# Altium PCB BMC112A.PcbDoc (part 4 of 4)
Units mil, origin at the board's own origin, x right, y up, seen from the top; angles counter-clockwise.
Board outline 5600 x 6100 mil, 8 copper layers (Top Layer, Signal Layer 1, Signal Layer 2, Signal Layer 3, Signal Layer 4, Signal Layer 5, Signal Layer 6, Bottom Layer), stack 62.048 mil thick; 366 components, 158 nets, 872 pads, 1045 vias.
Unrouted connection lines stored in the file: 4.
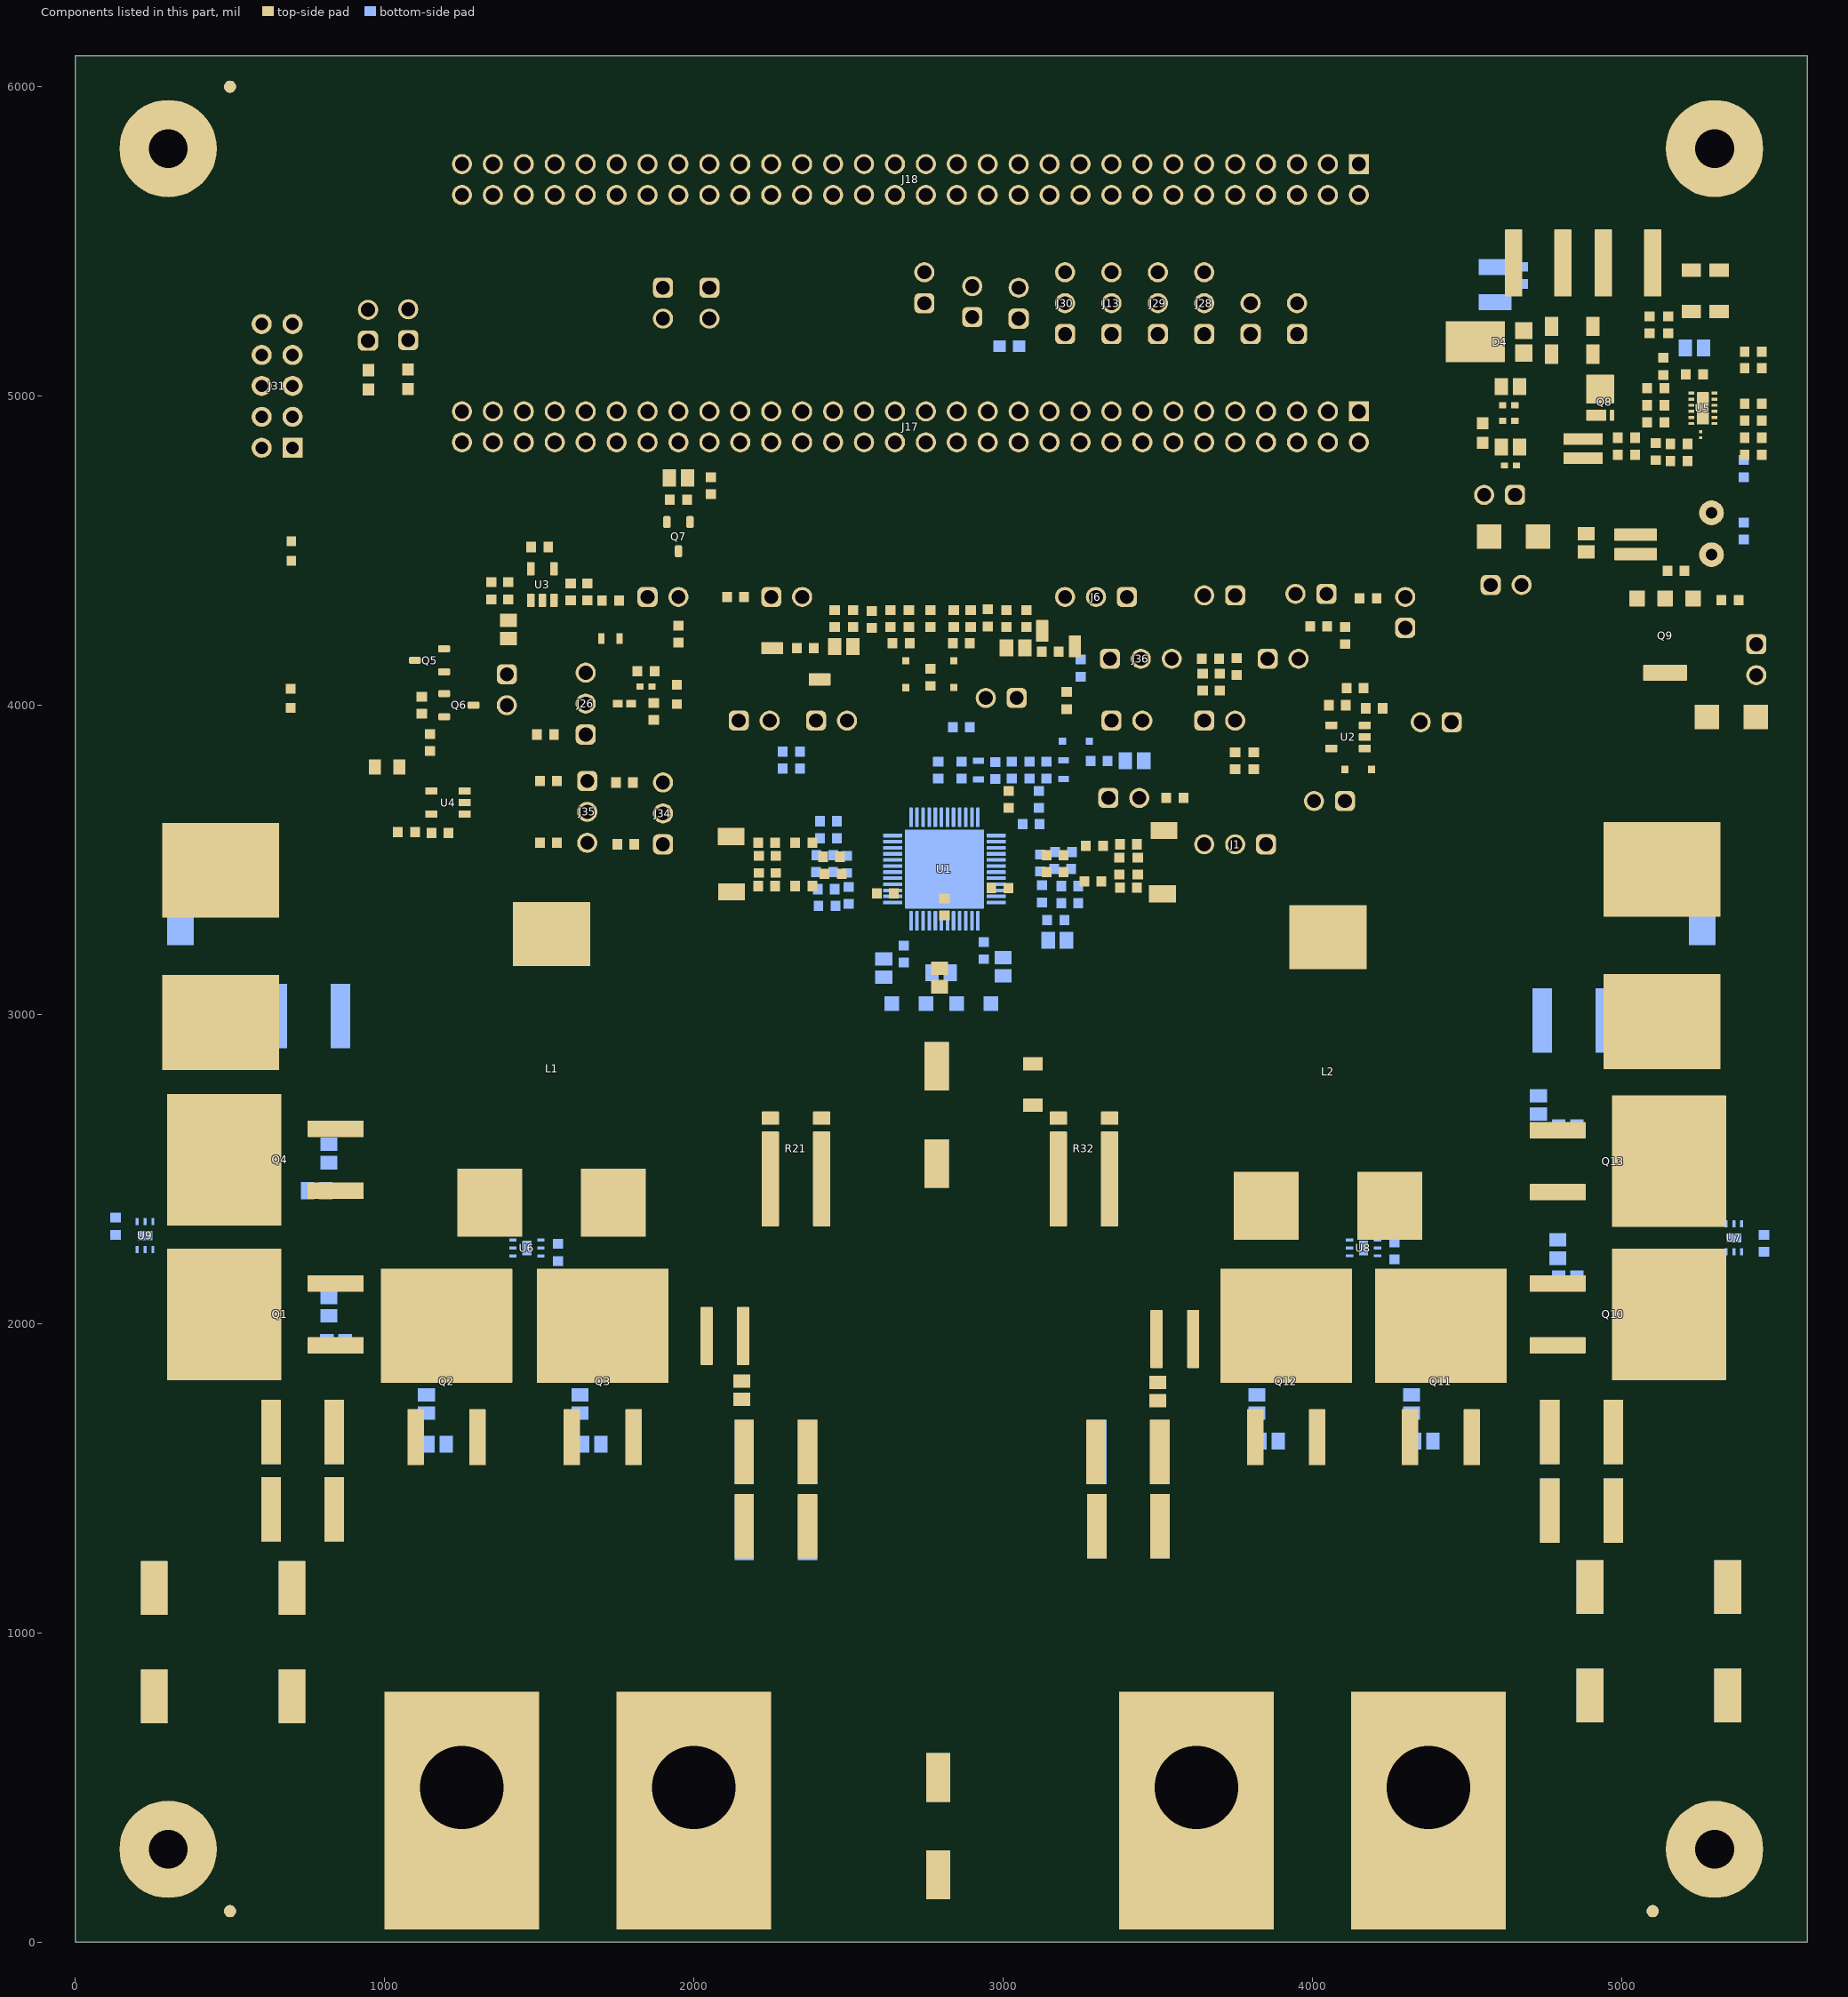
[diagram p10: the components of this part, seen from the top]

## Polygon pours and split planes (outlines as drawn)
NetC85_2 on Top Layer "TOP_LAYER_NETC85_2_P838" (solid, remove dead copper, pour order 838): 2092.06,3601.19 2137.72,3601.19 2137.72,3557.84 2092.06,3557.84
V48 on Top Layer "TOP_LAYER_V48_P849" (solid, remove dead copper, pour order 849): 1644.68,31.5 1644.41,31.77 1644.41,862.2 865.16,862.2 865.16,30
PGND on Top Layer "Signal Layer 1-PGND" (solid, remove dead copper, pour order 856): 5600,10 5600,6070 4390,6070 4390,5195 4390,3700 4030,3340 2820,3340 2310,3340 2140,3510 1055,3510 655,3910 655,6085 0,6085 0,10
AGND on Top Layer "Top Layer-AGND" (solid, remove dead copper, pour order 855): 1167.35,6076.65 667.38,6076.65 667.38,3921.65 1067.38,3521.65 1937.38,3521.65 2109.87,3349.15 4024.88,3349.15 4522.38,3846.65 4522.38,4339.46 4372.38,4489.46 4372.38,6076.65
V12 on Top Layer "Top Layer-V12" (solid, remove dead copper, pour order 854): 4015,25.26 3374.74,25.26 3040,360 2500,360 2315,545 2315,2730 3285,2730 3285,2280 3360,2205 3360,1540 3360,1220 3407.07,1172.93 3762.07,1172.93 4015,920
V48 on Top Layer "Top Layer-V48-2" (solid, remove dead copper, pour order 853): 5555,940 4891.63,940 4891.63,3130 5555,3130
V48 on Top Layer "Top Layer-V48-1" (solid, remove dead copper, pour order 852): 740,940 55,940 55,3130 740,3130
SW1 on Top Layer "Top Layer-No Net 10" (solid, remove dead copper, pour order 851): 2080,1840 2080,2200 2043.26,2236.74 1616.74,2236.74 1570,2283.49 1570,2750 1553.26,2766.74 786.74,2766.74 750,2730 750,1845 788.26,1806.74 2046.74,1806.74
SW2 on Top Layer "Top Layer-SW2" (solid, remove dead copper, pour order 850): 4020,2730 4020,2280 3973.67,2233.67 3608.67,2233.67 3570,2195 3570,1860 3620.47,1809.53 4804.53,1809.53 4881.33,1886.33 4881.33,2708.67 4816.33,2773.67 4063.67,2773.67
NetL2_1 on Top Layer "Top Layer-NetL2-1" (solid, remove dead copper, pour order 848): 3330,2260 3960,2260 3990,2290 3990,2740 3960,2770 3330,2770 3300,2740 3300,2290
NetL1_2 on Top Layer "Top Layer-NetL1-2" (solid, remove dead copper, pour order 847): 1620,2270 2270,2270 2295,2295 2295,2735 2270,2760 1620,2760 1600,2740 1600,2290
NetC48_2 on Top Layer "TOP_LAYER_NETC48_2_P846" (solid, remove dead copper, pour order 846): 4632.5,5260 4632.5,4895 4387.5,4895 4387.5,5260
NetC46_1 on Top Layer "TOP_LAYER_NETC46_1_P845" (solid, remove dead copper, pour order 845): 4990,4975 4860,4975 4835,5000 4835,5235 4900,5300 4900,5560 4920,5580 5000,5580 5015,5565 5015,5000
NetC42_1 on Top Layer "TOP_LAYER_NETC42_1_P844" (solid, remove dead copper, pour order 844): 5175,5240 5073.4,5240 5073.4,5553.4 5085,5565 5340,5565 5353.39,5551.61 5353.39,5383.39 5345,5375 5225,5375 5185,5335 5185,5250
NetC41_2 on Top Layer "TOP_LAYER_NETC41_2_P843" (solid, remove dead copper, pour order 843): 4710,5565 4710,5350 4810,5250 4810,5105 4800,5095 4665,5095 4655,5105 4655,5260 4605,5310 4605,5565 4615,5575 4700,5575
NetD7_1 on Top Layer "TOP_LAYER_NETD7_1_P841" (solid, remove dead copper, pour order 841): 5318.73,3892.98 4973.11,3892.98 4973.11,4250 5318.73,4250
AGND2 on Top Layer "TOP_LAYER_AGND2_P208" (solid, remove dead copper, pour order 842): 5435,5155 5435,4865 5195,4865 5195,4730 5500,4730 5500,5155
NetQ8_1-2-3 on Top Layer "TOP_LAYER_NETQ8_1-2-3_P840" (solid, remove dead copper, pour order 840): 4947.59,4955 4947.59,4895 4937.59,4885 4937.59,4841.65 4792.59,4841.65 4792.59,4955
AGND on Signal Layer 1 "SIGNAL_LAYER_1_AGND_P857" (solid, remove dead copper, pour order 857): 529.04,5293.81 779.35,5293.81 779.35,4682.49 529.45,4682.49
PGND on Signal Layer 1 "Signal Layer 1-Pgnd" (solid, remove dead copper, pour order 859): 5600,10 5600,6075 4540,6075 4395,6075 4390,5215 4393.1,3703.1 4030,3340 2820,3340 2310,3340 2140,3510 1055,3510 655,3910 655,6075 1155,6075 0,6075 0,10
AGND on Signal Layer 1 "Top Layer-Agnd" (solid, remove dead copper, pour order 858): 1169.97,6075 670,6075 670,3924.74 1070.17,3525.08 1938.79,3526.21 2112.76,3352.24 4027.24,3352.24 4525,3850 4525,4333.68 4375,4483.68 4375,5555 4375,6075
PGND on Signal Layer 2 "Signal Layer 1-pgnd" (solid, remove dead copper, pour order 866): 5600,20 5600,6080 4540,6080 4390,6080 4390,5198.17 4390,3700 4040,3350 2805,3350 2295,3350 2135,3510 1055,3510 655,3910 655,6080 1140,6080 0,6080 0,20
SW2 on Signal Layer 2 "SIGNAL_LAYER_2_SW2_P863" (solid, remove dead copper, pour order 863): 4850,2150 4650,2150 4650,1810 3500,1810 3500,2200 4020,2200 4020,2775 4850,2775
SW1 on Signal Layer 2 "SIGNAL_LAYER_2_SW1_P862" (solid, remove dead copper, pour order 862): 1885,1805 780,1805 750,1835 750,2735 780,2765 1495,2765 1570,2690 1570,2205 1875,2205 1920,2160 1920,1840
AGND on Signal Layer 2 "Top Layer-NetAGND 6" (solid, remove dead copper, pour order 865): 660,6070 660,3905 1060,3505 1930,3505 2102.76,3332.24 4017.24,3332.24 4515,3830 4515,4343.68 4375,4483.68 4375,6070
V12 on Signal Layer 2 "Top Layer-Net V1213" (solid, remove dead copper, pour order 864): 4015,25.26 3450,25.26 3115.26,360 2500,360 2315,545 2315,2730 3285,2730 3285,2280 3360,2205 3360,1215 3400,1175 3725,1175 4015,885
NetL2_1 on Signal Layer 2 "Signal Layer 2- NetL2-1 7" (solid, remove dead copper, pour order 861): 3410,2760 3980,2760 3995,2745 3995,2265 3975,2245 3415,2245 3395,2265 3395,2745
NetL1_2 on Signal Layer 2 "Signal Layer 2-NetL1-2 7" (solid, remove dead copper, pour order 860): 1630,2760 2175,2760 2200,2735 2200,2265 2180,2245 1620,2245 1600,2265 1600,2730
V48 on Signal Layer 3 "Signal Layer 3-V48" (solid, remove dead copper, pour order 871): 5600,25 1425,25 1420,30 0,30 0,2980 5600,2980
AGND on Signal Layer 3 "Top Layer-AGND 6" (solid, remove dead copper, pour order 870): 1121.31,6020.98 621.35,6020.98 621.35,3870.69 1021.37,3471.21 1894.94,3472.39 2069.11,3298.22 3978.58,3298.22 4476.35,3795.98 4476.35,4278.46 4326.35,4428.46 4326.35,6020.98
PGND on Signal Layer 3 "Signal Layer 3- PGND 1" (solid, remove dead copper, pour order 869): 4542.25,6075 5600,6075 5600,2995 0,2995 0,6075 1172.33,6075 655,6075 655,3910 1055,3510 1935,3510 2096.88,3348.12 4038.12,3348.12 4395,3705 4395,5195 4395,6075
SW1 on Signal Layer 3 "Top Layer-No Net 10" (solid, remove dead copper, pour order 868): 2080,1830 2080,2200 2050,2230 1630,2230 1600,2260 1600,2680 1565,2715 965,2715 932.64,2682.64 932.64,1827.36 960,1800 2050,1800
SW2 on Signal Layer 3 "Top Layer- NetSW-2 5" (solid, remove dead copper, pour order 867): 3995,2675 3995,2223.67 3613.67,2223.67 3570,2180 3570,1840 3606.33,1803.67 4633.67,1803.67 4670,1840 4670,2680 4635,2715 4035,2715
PGND on Signal Layer 4 "Signal Layer 1-PGND" (solid, remove dead copper, pour order 873): 5600.39,10 5600.39,6075 4389.93,6075 4389.93,3699.93 4030,3340 2820,3340 2105,3340 1930,3515 1050,3515 655,3910 655,6075 0,6075 0,10
AGND on Signal Layer 4 "Top Layer-AGND" (solid, remove dead copper, pour order 872): 1169.97,6075 670,6075 670,3924.65 1070.05,3525.15 1938.67,3526.33 2112.76,3352.24 4027.24,3352.24 4525,3850 4525,4333.68 4375,4483.68 4375,6075
V48 on Signal Layer 5 "Signal Layer 3-V48" (solid, remove dead copper, pour order 878): 5600.39,30 1430,30 1425,35 1.97,35 1.97,2980 5600.39,2980
AGND on Signal Layer 5 "Top Layer-AGND 6" (solid, remove dead copper, pour order 877): 1170,6075 670,6075 670,3930 1075,3525 1940,3525 2112.76,3352.24 4027.24,3352.24 4525.9,3850.9 4521.59,4325.1 4375,4487.4 4375,5570 4525,5730 4525,6075
PGND on Signal Layer 5 "Signal Layer 3-PGND 1" (solid, remove dead copper, pour order 876): 4392.17,6075 5600.39,6075 5600.39,2991 1.97,2991 1.97,6075 1155,6075 655,6075 655,3905 1050,3510 1935,3510 2102.3,3342.7 4032.7,3342.7 4388.6,3698.6
SW1 on Signal Layer 5 "Top Layer-SW1 10" (solid, remove dead copper, pour order 875): 2088.11,1838.11 2088.11,2199.88 2057.99,2230 1590,2230 1590,2660 1535,2715 980,2715 932.64,2667.64 932.64,1857.36 990,1800 2050,1800
SW2 on Signal Layer 5 "Top Layer-SW2 5" (solid, remove dead copper, pour order 874): 4010,2680 4010,2223.67 3598.48,2223.67 3566.89,2192.07 3566.89,1843.11 3606.33,1803.67 4623.67,1803.67 4670,1850 4670,2680 4630,2720 4050,2720
PGND on Signal Layer 6 "Signal Layer 6 PGND" (solid, remove dead copper, pour order 880): 5600.39,10 5600.39,6075 4389.93,6075 4389.93,3699.93 4030,3340 2820,3340 2105,3340 1935,3510 1055,3510 655,3910 655,6075 1155,6075 -3.94,6075 -3.94,10
AGND on Signal Layer 6 "Signal Layer 6 AGND" (solid, remove dead copper, pour order 879): 1170,6075 670,6075 670,3924.71 1070.08,3525.18 1938.62,3526.38 2112.76,3352.24 4027.24,3352.24 4525,3850 4525,4333.68 4375,4483.68 4375,6075
PGND on Bottom Layer "Bottom Layer PGND" (solid, remove dead copper, pour order 888): 5603.35,10 5603.35,6075 4390,6075 4390,3700 4030,3340 2820,3340 2105,3340 1935,3510 1055,3510 655,3910 655,6075 1.97,6075 1.97,10
AGND on Bottom Layer "Bottom Layer AGND" (solid, remove dead copper, pour order 887): 1169.97,6075 670,6075 670,3925 1070,3525 1940,3525 2113.45,3351.55 4026.55,3351.55 4525,3850 4525,4332.48 4375,4482.48 4375,6075
V12 on Bottom Layer "Top Layer-V12 3" (solid, remove dead copper, pour order 886): 4010,25.26 3374.74,25.26 3040,360 2510,360 2315,555 2315,2730 3285,2730 3285,2280 3360,2205 3360,1215 3405,1170 3765,1170 4010,925
V48 on Bottom Layer "Top Layer-V48 8" (solid, remove dead copper, pour order 885): 5555,940 4865,940 4865,3130 5555,3130
V48 on Bottom Layer "Top Layer-V48 7" (solid, remove dead copper, pour order 884): 740,940 55,940 55,3130 740,3130
SW1 on Bottom Layer "Top Layer-SW1" (solid, remove dead copper, pour order 883): 2080,1855.14 2080,2185.31 2030.31,2235 1615,2235 1570.56,2279.44 1570.56,2714.44 1520,2765 785,2765 750.56,2730.56 750.56,1879.44 825,1805 2029.86,1805
SW2 on Bottom Layer "Top Layer-SW2" (solid, remove dead copper, pour order 882): 4020,2730 4020,2276.56 3977.11,2233.67 3597.93,2233.67 3563.44,2199.18 3563.44,1846.56 3596.33,1813.67 4793.45,1813.67 4829.33,1849.55 4829.33,2737.28 4792.95,2773.67 4063.67,2773.67
AGND on Bottom Layer "Bottom Layer-AGND 1" (solid, remove dead copper, pour order 881): 2449.81,3335 2449.81,3634.81 2605,3790 3105,3790 3105,3195 3300,3195 3300,3910 2325,3910 2325,3335

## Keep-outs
Keep-Out Layer:
  the board outline again, w10
  text ".Layer_Name" at 373.26,-1656.72 h60

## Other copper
Top Layer:
  text ".Layer_Name" at 373.26,-1656.72 h60
Signal Layer 1:
  text ".Layer_Name" at 373.03,-1656.5 h60
Signal Layer 2:
  text ".Layer_Name" at 373.03,-1656.5 h60
Signal Layer 3:
  text ".Layer_Name" at 373.03,-1656.5 h60
Signal Layer 4:
  text ".Layer_Name" at 374.02,-1655.51 h60
Signal Layer 5:
  text ".Layer_Name" at 373.03,-1654.53 h60
Signal Layer 6:
  pour cut-out: 4720,5280 4740,5280 4750,5270 4750,5250 4740,5240 4720,5240 4710,5250 4710,5270
  text ".Layer_Name" at 374.02,-1654.53 h60
Bottom Layer:
  rectangle net AGND: 2792.61,3353.07 2852.61,3378.07
  pour cut-out: 4720,5280 4740,5280 4750,5270 4750,5250 4740,5240 4720,5240 4710,5250 4710,5270
  text ".Layer_Name" at 373.26,-1656.72 h60

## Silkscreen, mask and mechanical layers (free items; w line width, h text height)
Top Overlay:
  lines w7: 1119.25,5650 1181.69,5650 ; 1120.96,4849.54 1179.65,4849.54 ; 1955,5903.78 1955,5825 ; 4271.15,4846.45 4212.46,4846.45 ; 4280.43,5651.57 4221.74,5651.57 ; 5364.17,5212.13 5204.17,5202.13 ; 1179.65,4849.54 1160.14,4839.21 1160.35,4860.63 1179.65,4849.54 ; 1181.69,5650 1162.18,5638.91 1162.18,5661.09 1181.69,5650 ; 1955,5825 1964.78,5845 1945,5845 1955,5825 ; 4212.46,4846.45 4231.75,4835.36 4231.97,4856.78 4212.46,4846.45 ; 4221.74,5651.57 4241.03,5640.49 4241.25,5661.91 4221.74,5651.57 ; 5204.17,5202.13 5209.17,5207.13 5209.17,5197.13 5204.17,5202.13
  lines w10: 1162.65,1329.49 1161.94,1181.14 1790.6,1181.14 ; 1163.29,1331.38 1791.95,1331.38 ; 1791.26,1182.48 1791.98,1330.83 ; 3850.5,1329.25 3849.78,1180.91 4478.44,1180.91 ; 3851.13,1331.15 4479.79,1331.15 ; 4479.11,1182.25 4479.82,1330.59
  text "KEY" at 1280,5840 h40 r90
  text "DIR" at 3760,5840 h40 r90
  text "10V" at 2075,5835 h40 r90
  text "SDA" at 2275,5835 h40 r90
  text "ISETD" at 3580,5835 h40 r90
  text "ISETA" at 3670,5835 h40 r90
  text "SCL" at 2170,5830 h40 r90
  text "OPT" at 3270,5830 h40 r90
  text "V48_X" at 4175,5830 h40 r90
  text "SD_CMD_S" at 1819.7,5825 h40 r45
  text "IOUT1_X" at 2670,5825 h40 r90
  text "IOUT1_S" at 2875,5825 h40 r90
  text "5.0V" at 2970,5825 h40 r90
  text "CH1_S" at 3870,5825 h40 r90
  text "EN_S" at 3965,5825 h40 r90
  text "V12_X" at 4070,5825 h40 r90
  text "SECONDARY" at 4232.28,5825 h40
  text "PGND" at 2375,5820 h40 r90
  text "AGND" at 2470,5820 h40 r90
  text "IOUT2_X" at 2570,5820 h40 r90
  text "IOUT2_S" at 2770,5820 h40 r90
  text "DEM S" at 3075,5820 h40 r90
  text "CH2_S" at 3180,5820 h40 r90
  text "SYNIN_S" at 3470,5820 h40 r90
  text "SYNOT_S" at 3375,5815 h40 r90
  text "GND ROW" at 4300.29,5635.92 h35
  text "GND ROW" at 871.83,5634.58 h35
  text "4XPH" at 2670,5480 h40
  text "EN1" at 3520,5480 h40 r90
  text "EN2" at 3220,5470 h40 r90
  text "SYN" at 3370,5470 h40 r90
  text "DIR" at 3660,5470 h40 r90
  text "SSDEM" at 2851.81,5415 h40 r45
  text "SQIN" at 3060,5415 h40 r90
  text "SDA" at 899.73,5379.09 h35
  text "SCL" at 1040.59,5377.41 h35
  text "CH1_S" at 3820,5370 h40 r90
  text "EN_S" at 3960,5370 h40 r90
  text "10.0V" at 2160,5330 h40 r90
  text "nSD" at 1830,5300 h40 r90
  text "AGND" at 2470,5040 h40 r90
  text "PRIMARY" at 4181.45,5037.8 h40
  text "10V" at 2070,5030 h40 r90
  text "SDA" at 2270,5030 h40 r90
  text "PGND" at 2370,5030 h40 r90
  text "IOUT2_S" at 2570,5030 h40 r90
  text "IOUT1_S" at 2670,5030 h40 r90
  text "SD_CMD" at 1995,5025 h40 r90
  text "KEY" at 1270,5020 h40 r90
  text "SD_CMD_S" at 1370,5020 h40 r90
  text "SYNCOUT_S" at 1470,5020 h40 r90
  text "SYNCIN_S" at 1570,5020 h40 r90
  text "CH2_S" at 1670,5020 h40 r90
  text "CH1_S" at 1770,5020 h40 r90
  text "EN_S" at 1870,5020 h40 r90
  text "SCL" at 2170,5020 h40 r90
  text "GND ROW" at 864.23,4834.58 h35
  text "GND" at 4284.58,4828.8 h35
  text "EN1" at 3870,4680 h40 r90
  text "EN2" at 3170,4670 h40 r90
  text "DIR" at 3770,4670 h40 r90
  text "OPT" at 3265,4665 h40 r90
  text "5.0V" at 2980,4630 h40 r90
  text "DEM" at 3080,4630 h40 r90
  text "UVLO" at 3972.17,4624.13 h40 r90
  text "IOUT1" at 2870,4620 h40 r90
  text "SP_BIAS" at 4256.81,4603.5 h40
  text "IOUT2" at 2765,4595 h40 r90
  text "ISETD" at 3570,4590 h40 r90
  text "ISETA" at 3670,4590 h40 r90
  text "V12SNS" at 4079.96,4555.43 h40 r90
  text "SYNCIN" at 3470,4550 h40 r90
  text "V48SNS" at 4180.22,4550 h40 r90
  text "SYNCOUT" at 3370,4510 h40 r90
  text "BODE" at 5485,4493.76 h40 r90
  text "DITH" at 3925,4435 h40
  text "BUCK" at 534.35,4430.88 h40 r90
  text "MODE" at 623.79,4430.88 h40 r90
  text "EN1-2" at 3605,4425 h40
  text "OPT" at 3250,4420 h40
  text "SD" at 1815,4410 h40
  text "SYNCOUT" at 2160,4410 h40
  text "EXT 11V" at 4726.22,4368.12 h40
  text "DEM/PWM" at 4371.42,4221.41 h40
  text "ISETA" at 3350,4210 h40
  text "ISET-PWM" at 4005,4119.69 h40
  text "IOUT1-2" at 3255,4015 h40
  text "AUX BIAS" at 5549,4015.14 h35 r90
  text "CCIN" at 4350,4010 h40
  text "MODE" at 623.79,3959.84 h40 r90
  text "OTEMP" at 1580,3960 h40 r90
  text "SS/DEM1" at 1498.35,3945.55 h40 r90
  text "BOOST" at 534.35,3940.94 h40 r90
  text "IOUT2" at 3825,3905 h40
  text "VSET" at 2927.65,3846.73 h40
  text "OTEMP LED" at 2035,3790 h40 r90
  text "IOUT1" at 2108.61,3784.47 h40
  text "IOUT1_S" at 2326.41,3776.73 h40
  text "BIAS/UV" at 3255,3765 h40
  text "AUX" at 4460,3735 h40
  text "12 VIN 48" at 3580,3620 h40
  text "CCCTL" at 3970.49,3584.92 h40
  text "CFG1" at 1844.78,3402.23 h35
  text "CFG2" at 1661,3398.92 h35
  text "60A MAX" at 1206.89,1217.13 h80
  text "60A MAX" at 3894.73,1216.89 h80
  text ".PRJ_Title" at 2369.62,1038.39 h60
  text "48VDC" at 1436.89,1003.94 h80
  text "12VDC" at 3820.87,1003.94 h80
  text "+" at 1238.54,991.79 h120
  text "-" at 1922.46,985 h120
  text "-" at 4330,977.29 h120
  text "+" at 3602.24,968.38 h120
  text ".PRJ_Number" at 2367.65,910.43 h40
  text "REV..PCB_Rev" at 2367.65,839.57 h40
  text ".Layer_Name" at 373.26,-1656.72 h60
Bottom Overlay:
  lines w7: 1120.37,5650.4 1179.06,5650.4 ; 1121.82,4846.52 1180.51,4846.52 ; 1179.06,5650.4 1159.77,5661.49 1159.55,5640.07 1179.06,5650.4 ; 1180.51,4846.52 1161.22,4857.61 1161,4836.18 1180.51,4846.52
  text "IOUT2_X" at 2560,6080 h40 r90
  text "IOUT1_X" at 2660,6075 h40 r90
  text "IOUT2_S" at 2760,6075 h40 r90
  text "V48_X" at 4165,6075 h40 r90
  text "IOUT1_S" at 2865,6070 h40 r90
  text "V12_X" at 4060,6070 h40 r90
  text "SYNIN_S" at 3470.53,6067.43 h40 r90
  text "PGND" at 2365,6065 h40 r90
  text "AGND" at 2460,6065 h40 r90
  text "SYNOT_S" at 3374.71,6065 h40 r90
  text "ISETD" at 3587.11,6031.5 h40 r90
  text "nFAULTS" at 2021.65,6019.69 h40 r45
  text "DEM S" at 3076.77,6017.72 h40 r90
  text "ISETA" at 3670,6017.72 h40 r90
  text "CH2_S" at 3178.58,6006.89 h40 r90
  text "CH1_S" at 3865.16,6006.89 h40 r90
  text "EN_S" at 3970,5973.43 h40 r90
  text "SDA" at 2275,5956.22 h40 r90
  text "5.0V" at 2974.71,5956.22 h40 r90
  text "SCL" at 2171.42,5952.71 h40 r90
  text "OPT" at 3271.42,5948.54 h40 r90
  text "KEY" at 1280,5945.35 h40 r90
  text "DIR" at 3760.84,5939.96 h40 r90
  text "10V" at 2073.09,5930 h40 r90
  text "GND ROW" at 1099.87,5638.16 h35
  text "SYN" at 3370,5580 h40 r90
  text "EN2" at 3220,5570 h40 r90
  text "DIR" at 3660,5570 h40 r90
  text "3.3V" at 3060,5560 h40 r90
  text "EN1" at 3520,5560 h40 r90
  text "SSDEM" at 2987.11,5545 h40 r45
  text "CH1S" at 3820,5510 h40 r90
  text "10.0V" at 2160,5500 h40 r90
  text "EN" at 3960,5430 h40 r90
  text "nSD" at 1830,5412.98 h40 r90
  text "SYNCOUT_S" at 1470,5380 h40 r90
  text "nFAULT_S" at 1370,5340.01 h40 r90
  text "SYNCIN_S" at 1570,5333.35 h40 r90
  text "IOUT2_S" at 2570,5293.36 h40 r90
  text "IOUT1_S" at 2670,5286.7 h40 r90
  text "CH2_S" at 1670,5220.05 h40 r90
  text "PDGND" at 2370,5220.05 h40 r90
  text "CH1_S" at 1770,5213.39 h40 r90
  text "IOUT2" at 2770,5213.39 h40 r90
  text "EN_S" at 1870,5180.06 h40 r90
  text "nFLT" at 1960,5180.06 h40 r90
  text "AGND" at 2470,5180.06 h40 r90
  text "SDA" at 2270.63,5141.81 h40 r90
  text "KEY" at 1270,5140.08 h40 r90
  text "10V" at 2070,5133.41 h40 r90
  text "SCL" at 2171.42,5133.41 h40 r90
  text "GND ROW" at 1095.3,4834.58 h35
  text "IOUT1" at 2870,4780 h40 r90
  text "5.0V" at 2980,4770 h40 r90
  text "3.3V" at 3080,4770 h40 r90
  text "CH2" at 3170,4770 h40 r90
  text "SYNCOUT" at 3370,4770 h40 r90
  text "SYNCIN" at 3470,4770 h40 r90
  text "ISETD" at 3570,4770 h40 r90
  text "ISETA" at 3670,4770 h40 r90
  text "DIR" at 3770,4770 h40 r90
  text "CH1" at 3870,4770 h40 r90
  text "EN" at 3970,4770 h40 r90
  text "V12SN" at 4080,4770 h40 r90
  text "V48SN" at 4180,4770 h40 r90
  text "SP_BIAS" at 4516.42,4603.5 h40
  text "J24" at 3757.29,4500 h40
  text "J3" at 1894.15,4474.13 h40
  text "DITH" at 4065.84,4434.86 h40
  text "J6" at 3425.36,4426.81 h40
  text "OPT" at 3305.84,4422.56 h40
  text "EN1-2" at 3781.73,4422.56 h40
  text "SYNCOUT" at 2425,4410 h40
  text "SD" at 1881.1,4405 h40
  text "EXT 11V" at 4984.49,4366.73 h40
  text "J5" at 4445,4284.86 h40
  text "DEM/PWM" at 4636.06,4220.53 h40
  text "ISETA" at 3536.3,4211.73 h40
  text "SS/DEM1" at 1501.3,4200 h40 r90
  text "OTEMP" at 1585,4145 h40 r90
  text "J37" at 3039.24,4139.26 h40
  text "ISET-PWM" at 4309.29,4119.7 h40
  text "J16" at 2495,4096.14 h40
  text "J2" at 2235,4078.5 h40
  text "VSET" at 3071.21,4077.64 h40
  text "IOUT1-2" at 3540,4020 h40
  text "IOUT1_S" at 2607.15,4016.81 h40
  text "CCIN" at 4492.71,4010.83 h40
  text "IOUT1" at 2263.97,4000 h40
  text "J7" at 3885.87,3957.88 h40
  text "IOUT2" at 3993.38,3890.85 h40
  text "J1" at 3785,3675 h40
  text "48 VIN 12" at 3910,3620 h40
  text "CCCTL" at 4151.46,3600 h40
  text "J21" at 4273.63,3597.9 h40
  text "CFG1" at 1963.64,3414.62 h60
  text "CFG2" at 1735.81,3401.22 h35
  text "48VDC" at 1806.22,1003.94 h80
  text "12VDC" at 4205.95,1000 h80
  text "+" at 1315,985 h120
  text "-" at 2006.89,978.35 h120
  text "-" at 4407.52,973.78 h120
  text "+" at 3683.54,968.38 h120
  text ".Layer_Name" at 373.26,-1656.72 h60
Top Paste:
  text ".Layer_Name" at 373.26,-1656.72 h60
Bottom Paste:
  text ".Layer_Name" at 373.26,-1656.72 h60
Top Solder:
  text ".Layer_Name" at 373.26,-1656.72 h60
  text ".Layer_Name" at 373.26,-1656.72 h60
Bottom Solder:
  text ".Layer_Name" at 373.26,-1656.72 h60
Drill Guide:
  text ".Layer_Name" at 373.26,-1656.72 h60
M1 Board Outline:
  the board outline again, w10
  text ".Layer_Name" at 373.26,-1656.72 h60
M2 Board Dimensions:
  rectangle: -78.74,-1198.23 296.26,-1073.23
  rectangle: -203.74,-1073.23 -78.74,-948.23
  lines w7: -203.74,-1073.23 796.26,-1073.23 ; -78.74,-1198.23 -78.74,-948.23 ; 46.26,-1198.23 46.26,-948.23 ; 296.26,-1198.23 296.26,-948.23 ; 546.26,-1198.23 546.26,-948.23 ; -203.74,-1198.23 -203.74,-948.23 796.26,-948.23 796.26,-1198.23 -203.74,-1198.23
  text ".Layer_Name" at 373.26,-1656.72 h60
M3 3D STEP Top:
  text ".Layer_Name" at 373.26,-1656.72 h60
M4 3D STEP Bottom:
  text ".Layer_Name" at 373.26,-1656.72 h60
M5 Assembly Top:
  lines w10: -495.74,-1728.4 6104.26,-1728.4 ; -495.74,-1525.06 6106.26,-1525.06 ; -495.74,-1321.73 -495.74,-1931.73 3509.26,-1931.73 6106.26,-1931.73 6106.26,-1321.73 -495.24,-1321.73 -495.24,-1931.73 1080.26,-1931.73 ; 1969.26,-1931.73 1969.26,-1321.73 ; 3236.26,-1525.06 3236.26,-1321.73 ; 4076.26,-1525.06 4076.26,-1321.73 ; 4698.26,-1938.23 4698.26,-1735.4
  text "COMPONENTS MARKED 'DNP' SHOULD NOT BE POPULATED." at 256.65,-1105.9 h60
  text "COMPONENTS MARKED 'DNP' SHOULD NOT BE POPULATED." at 949.76,-1116.73 h60
  text "ASSEMBLY VARIANT:" at 256.15,-1221.4 h60
  text ".VariantName" at 1292.15,-1221.4 h60
  text "ASSEMBLY VARIANT:" at 949.26,-1232.23 h60
  text ".VariantName" at 1985.26,-1232.23 h60
  text "PCB VIEWED FROM TOP SIDE" at -432.24,-1453.9 h60
  text "BOARD #:" at 2044.26,-1453.9 h60
  text ".PRJ_Number" at 2589.76,-1453.9 h60
  text "REV:" at 3434.26,-1453.9 h60
  text ".PCB_Rev" at 3725.76,-1453.9 h60
  text "SVN REV:" at 4272.26,-1453.9 h60
  text ".VersionControl_RevNumber" at 4778.26,-1453.9 h60
  text ".Layer_Name" at 373.26,-1656.5 h60
  text "PLOT NAME =" at -432.24,-1862.56 h60
  text ".plot_File_Name" at 373.26,-1862.56 h60
  text "GENERATED    :" at 2046.26,-1862.56 h60
  text ".Print_Date" at 2915.76,-1862.56 h60
  text ".Print_Time" at 3644.76,-1862.56 h60
  text "TEXAS INSTRUMENTS" at 4909.26,-1862.56 h60
M6 Assembly Bottom:
  lines w10: -496.24,-1525.56 6105.76,-1525.56 ; -494.24,-1728.9 6105.76,-1728.9 ; 911.76,-1938.73 911.76,-1735.9 ; 1533.76,-1525.56 1533.76,-1322.23 ; 2373.76,-1525.56 2373.76,-1322.23 ; 3640.76,-1932.23 3640.76,-1322.23 ; 4529.76,-1932.23 6105.26,-1932.23 6105.26,-1322.23 -496.24,-1322.23 -496.24,-1932.23 2100.76,-1932.23 6105.76,-1932.23 6105.76,-1322.23
  text "COMPONENTS MARKED 'DNP' SHOULD NOT BE POPULATED." at 5205.15,-1105.4 h60
  text "COMPONENTS MARKED 'DNP' SHOULD NOT BE POPULATED." at 5898.26,-1116.23 h60
  text ".VariantName" at 4161.15,-1221.4 h60
  text "ASSEMBLY VARIANT:" at 5200.15,-1221.4 h60
  text ".VariantName" at 4854.26,-1232.23 h60
  text "ASSEMBLY VARIANT:" at 5893.26,-1232.23 h60
  text ".VersionControl_RevNumber" at 831.76,-1454.4 h60
  text "SVN REV:" at 1337.76,-1454.4 h60
  text ".PCB_Rev" at 1884.26,-1454.4 h60
  text "REV:" at 2175.76,-1454.4 h60
  text ".PRJ_Number" at 3020.26,-1454.4 h60
  text "BOARD #:" at 3565.76,-1454.4 h60
  text "PCB VIEWED FROM BOTTOM SIDE" at 6042.26,-1454.4 h60
  text ".Layer_Name" at 373.03,-1654.53 h60
  text "TEXAS INSTRUMENTS" at 700.76,-1863.06 h60
  text ".Print_Time" at 1965.26,-1863.06 h60
  text ".Print_Date" at 2694.26,-1863.06 h60
  text "GENERATED    :" at 3563.76,-1863.06 h60
  text ".plot_File_Name" at 5236.76,-1863.06 h60
  text "PLOT NAME =" at 6042.26,-1863.06 h60
M9 Title Sheet:
  drawing of 55 lines, arcs and shapes, not listed
  text "1" at 854.6,12583.16 h70
  text "2" at 4180.26,12583.16 h70
  text "3" at 7510.26,12583.16 h70
  text "4" at 10845.26,12583.16 h70
  text "5" at 14170.26,12583.16 h70
  text "6" at 17505.26,12583.16 h70
  text "A" at -666.74,10805.16 h70
  text "A" at 19033.26,10805.16 h70
  text "B" at -666.74,7055.16 h70
  text "B" at 19033.26,7055.16 h70
  text "C" at -666.74,3305.16 h70
  text "C" at 19033.26,3305.16 h70
  text "D" at -666.74,-444.84 h70
  text "D" at 19033.26,-444.84 h70
  text "PROJECT TITLE:" at 15939.26,-529.84 h45
  text ".PRJ_Title" at 15989.26,-663.17 h70
  text "DESIGNED FOR:" at 15939.26,-830.84 h45
  text ".PRJ_Customer" at 15989.26,-970.84 h70
  text "FILE NAME:" at 15939.26,-1130.84 h45
  text ".PCB_File_Name_No_Path" at 15989.26,-1250.84 h70
  text "Texas Instruments (TI) and/or its licensors do not warrant the accuracy or completeness of this specification" at 10969.76,-1412.68 h45
  text "ENGINEER:" at 15939.26,-1420.84 h45
  text "LAYOUT BY:" at 17444.26,-1420.84 h45
  text "or any information contained therein. TI and/or its licensors do not warrant that this design will meet" at 10924.77,-1525.34 h45
  text ".PRJ_Engineer" at 15989.26,-1575.83 h70
  text ".PCB_Layout" at 17494.76,-1575.83 h70
  text "the specifications, will be suitable for your application or fit for any particular purpose, or will operate in" at 10924.77,-1638.01 h45
  text ".Layer_Name" at 373.26,-1656.72 h60
  text "ALTIUM DESIGNER VERSION:" at 17444.26,-1730.84 h45
  text "an implementation. TI and/or its licensors do not warrant that the design is production worthy. You should" at 10924.77,-1750.67 h45
  text "completely validate and test your design implementation to confirm the system functionality for your application." at 10969.76,-1863.34 h45
  text ".print_Scale" at 15989.26,-1864.17 h70
  text ".Application_BuildNumber" at 17494.76,-1864.17 h70
  text "1" at 854.6,-2116.84 h70
  text "2" at 4180.26,-2116.84 h70
  text "3" at 7510.26,-2116.84 h70
  text "4" at 10845.26,-2116.84 h70
  text "5" at 14170.26,-2116.84 h70
  text "6" at 17505.26,-2116.84 h70
M10 Fab Notes:
  drawing of 189 lines, arcs and shapes, not listed
  text "DESIGN INFORMATION" at 16975.8,5562.93 h60
  text "MIN. TRACK WIDTH:" at 16331.24,5430.8 h60
  text "8" at 17427.48,5430.81 h60
  text "MIL" at 17582.24,5430.8 h60
  text "7.874" at 17261.1,5309.12 h60
  text "MIN. CLEARANCE:" at 16331.24,5306.68 h60
  text "MIL" at 17582.24,5306.68 h60
  text "19.685" at 17210.63,5185.04 h60
  text "MIN. VIA PAD SIZE:" at 16331.24,5182.55 h60
  text "MIL" at 17582.24,5182.55 h60
  text "0.05mm (2MIL)" at 17026.24,5052.65 h60
  text "MINIMUM ANNULAR RING" at 16002.01,5044.43 h60
  text "EXTERNAL" at 17734.24,5044.43 h60
  text "PER" at 16202.01,4934.3 h60
  text "IPC-D-275 CLASS 2 LEVEL C" at 16422.01,4934.3 h60
  text "MIL, HOLES" at 17910.24,4833.82 h60
  text "+/-" at 17517.78,4825.24 h60
  text "+/-" at 18371.78,4825.24 h60
  text "REGISTRATION TOLERANCES:" at 16002.01,4824.17 h60
  text "METAL" at 17201.78,4824.17 h60
  text "5" at 17777.98,4824.18 h60
  text "3" at 18610.98,4824.18 h60
  text "MIL" at 18727.24,4824.17 h60
  text "HOLE SIZE TOLERANCE (UNLESS OTHERWISE SPECIFIED):" at 16002.01,4725.86 h60
  text "+/-" at 18371.78,4722.99 h60
  text "3" at 18610.98,4721.93 h60
  text "MIL" at 18727.24,4721.92 h60
  text "MATERIAL:" at 15927.24,4584.28 h60
  text "FR-4 High Tg" at 16913.68,4455.75 h60
  text "X" at 16769.24,4447.76 h60
  text "FR-4" at 16348.24,4443.24 h60
  text "OTHER" at 17836.24,4443.24 h60
  text "62 MIL (1.6mm) +/-10%" at 16668.34,4300.22 h60
  text "X" at 16548.24,4297.76 h60
  text "THICKNESS:" at 16002.01,4291.99 h60
  text "OTHER" at 17953.24,4291.99 h60
  text "TOLERANCE:" at 16002.01,4153.68 h60
  text "X" at 16850.24,4153.68 h60
  text "ANSI IPC-6012 TYPE 3 CLASS 2" at 17028.26,4153.68 h60
  text "OTHER +/-" at 17028.24,4009.49 h60
  text "BOW & TWIST:" at 16002.01,3864.3 h60
  text "X" at 16850.24,3864.3 h60
  text "ANSI IPC-6012 TYPE 3 CLASS 2" at 17028.26,3864.3 h60
  text "OTHER +/-" at 17028.24,3717.6 h60
  text "DRILLING:" at 15927.24,3586.99 h60
  text "NC_DRILL FILES" at 17688.24,3481.8 h60
  text "REFERENCE:" at 16002.01,3477.86 h60
  text "X" at 16659.24,3477.76 h60
  text "AS SHOWN" at 16837.24,3477.86 h60
  text "X" at 17560.24,3477.86 h60
  text "OTHER" at 17986.24,3335.61 h60
  text "PTH COPPER THICKNESS:" at 16001.69,3332.08 h60
  text "X" at 17140.92,3332.08 h60
  text "20-30 um" at 17268.92,3332.08 h60
  text "BOARD FINISH:" at 15927.24,3184.48 h60
  text "SILKSCREEN:" at 16082.46,3074.36 h60
  text "X" at 17040.24,3074.36 h60
  text "TOP" at 17157.24,3074.36 h60
  text "BOTTOM" at 17668.24,3074.36 h60
  text "X" at 17544.18,3072.83 h60
  text "SILKSCREEN COLOR:" at 16082.46,2919.17 h60
  text "X" at 17039.24,2919.17 h60
  text "WHITE" at 17157.24,2919.17 h60
  text "OTHER" at 17668.24,2919.17 h60
  text "X" at 17170.24,2775.72 h60
  text "GREEN" at 17288.24,2775.72 h60
  text "OTHER" at 17906.24,2775.72 h60
  text "SOLDER RESIST COLOR:" at 16082.46,2768.85 h60
  text "X" at 17170.24,2621.47 h60
  text "MATTE" at 17288.24,2621.47 h60
  text "SEMI-GLOSS" at 17905.78,2620.83 h60
  text "IMMERSION GOLD (ENIG)" at 16988.24,2448.69 h60
  text "ENEPIG" at 18325.78,2441.47 h60
  text "SURFACE FINISH:" at 15927.24,2440.47 h60
  text "X" at 16810.24,2440.47 h60
  text "IMM. TIN/SILVER OR EQUIV" at 16256.78,2303.16 h60
  text "OTHER" at 17688.24,2299.22 h60
  text "ARRAY/PANEL:" at 15927.24,2143.84 h60
  text "CUT AND TRIM PER M1 BOARD OUTLINE" at 16988.24,2135.62 h60
  text "N.C. ROUTE" at 16988.24,1999.65 h60
  text "X" at 17676.24,1999.65 h60
  text "V. SCORE" at 17854.24,1999.65 h60
  text "CERTIFICATION:" at 15927.24,1870.53 h60
  text "MATERIALS AND WORKMANSHIP FOR ALL PCBS" at 16652.24,1870.53 h60
  text "TO MEET OR EXCEED THE REQUIREMENTS OF:" at 16652.24,1776.47 h60
  text "X" at 16289.75,1647.84 h60
  text "ANSI IPC-A-600F CLASS ->" at 16417.74,1647.84 h60
  text "X" at 18065.75,1647.84 h60
  text "2" at 18175.74,1647.84 h60
  text "1" at 17860.74,1646.34 h60
  text "3" at 18529.74,1646.34 h60
  text "X" at 17101.75,1500.15 h60
  text "RoHS" at 17229.74,1500.15 h60
  text "OTHER" at 17874.14,1500.15 h60
  text "PER ORDER" at 18271.2,1500.15 h60
  text "ALL BOARDS MUST MEET OR EXCEED UL94-V0 REQUIREMENTS." at 15954.78,1346.32 h60
  text "PCB MUST BEAR THE UL94V-0 UL REGISTERED MATERIAL ID NUMBER" at 15954.78,1230.26 h60
  text "ADDITIONAL REQUIREMENTS:" at 15927.24,1060.84 h60
  text "MICROSECTION:" at 16002.01,953.71 h60
  text "YES" at 16907.74,953.71 h60
  text "REQUIRED" at 17769.24,809.38 h60
  text "BARE BOARD ELEC. TEST:" at 16002.01,806.52 h60
  text "NONE" at 17307.74,806.52 h60
  text "X" at 17651.24,806.52 h60
  text "PER ORDER" at 18361.24,806.52 h60
  text "X" at 16052.32,661.91 h60
  text "8 MIL VIAS REQUIRE NON-CONDUCTIVE FILL AND PLANARIZE" at 16170.16,601.57 h59
  text "XX MIL VIAS REQUIRE CONDUCTIVE FILL AND PLANARIZE" at 16178.16,497.6 h60
  text "OUTER XX MIL TRACES REQUIRE 50 OHM SINGLE-ENDED IMPEDANCE" at 16177.17,334.21 h58
  text "LAYER 2 & 3 (INNER LAYERS) XX MIL WIDE, XX MIL SPACE / TRACES REQUIRE 100 OHM DIFFERENTIAL IMPEDANCE" at 16169.17,98.5 h60
  text ".Layer_Name" at 373.26,-1656.72 h60
M11 Gerber Information:
  lines w10: -495.74,-1728.4 6104.26,-1728.4 ; -495.74,-1525.06 6106.26,-1525.06 ; -495.74,-1321.73 -495.74,-1931.73 3509.26,-1931.73 6106.26,-1931.73 6106.26,-1321.73 -495.24,-1321.73 -495.24,-1931.73 1080.26,-1931.73 ; 1969.26,-1931.73 1969.26,-1321.73 ; 3236.26,-1525.06 3236.26,-1321.73 ; 4076.26,-1525.06 4076.26,-1321.73 ; 4698.26,-1938.23 4698.26,-1735.4
  text "ALL ARTWORK VIEWED FROM TOP SIDE" at -432.24,-1453.9 h60
  text "BOARD #:" at 2044.26,-1453.9 h60
  text ".PRJ_Number" at 2589.76,-1453.9 h60
  text "REV:" at 3434.26,-1453.9 h60
  text ".PCB_Rev" at 3725.76,-1453.9 h60
  text "SVN REV:" at 4272.26,-1453.9 h60
  text ".VersionControl_RevNumber" at 4778.26,-1453.9 h60
  text "LAYER NAME =" at -432.24,-1656.72 h60
  text "PLOT NAME =" at -432.24,-1862.56 h60
  text ".plot_File_Name" at 373.26,-1862.56 h60
  text "GENERATED    :" at 2046.26,-1862.56 h60
  text ".Print_Date" at 2915.76,-1862.56 h60
  text ".Print_Time" at 3644.76,-1862.56 h60
  text "TEXAS INSTRUMENTS" at 4909.26,-1862.56 h60
M12 Stackup:
  drawing of 503 lines, arcs and shapes, not listed
  text "Layer" at 14401.32,12293.25 h60
  text "Name" at 14811.23,12293.25 h60
  text "Material" at 15750.97,12293.25 h60
  text "Thickness" at 16610.74,12293.25 h60
  text "Constant" at 17260.58,12293.25 h60
  text "Board Layer Stack" at 17830.44,12293.25 h60
  text "Top Overlay" at 14811.23,12173.25 h60
  text "Top Solder" at 14811.23,12053.25 h60
  text "Solder Resist" at 15750.97,12053.25 h60
  text "0.40mil" at 16610.74,12053.25 h60
  text "3.5" at 17260.58,12053.25 h60
  text "1" at 14401.32,11933.25 h60
  text "Top Layer" at 14811.23,11933.25 h60
  text "2.76mil" at 16610.74,11933.25 h60
  text "Dielectric1" at 14811.23,11813.25 h60
  text "FR-4 High Tg" at 15750.97,11813.25 h60
  text "5.00mil" at 16610.74,11813.25 h60
  text "4.8" at 17260.58,11813.25 h60
  text "2" at 14401.32,11693.25 h60
  text "Signal Layer 1" at 14811.23,11693.25 h60
  text "2.76mil" at 16610.74,11693.25 h60
  text "Dielectric2" at 14811.23,11573.25 h60
  text "FR-4 High Tg" at 15750.97,11573.25 h60
  text "5.00mil" at 16610.74,11573.25 h60
  text "4.8" at 17260.58,11573.25 h60
  text "3" at 14401.32,11453.25 h60
  text "Signal Layer 2" at 14811.23,11453.25 h60
  text "2.76mil" at 16610.74,11453.25 h60
  text "Dielectric3" at 14811.23,11333.25 h60
  text "FR-4 High Tg" at 15750.97,11333.25 h60
  text "5.00mil" at 16610.74,11333.25 h60
  text "4.8" at 17260.58,11333.25 h60
  text "4" at 14401.32,11213.25 h60
  text "Signal Layer 3" at 14811.23,11213.25 h60
  text "2.76mil" at 16610.74,11213.25 h60
  text "Dielectric7" at 14811.23,11093.25 h60
  text "FR-4 High Tg" at 15750.97,11093.25 h60
  text "10.00mil" at 16610.74,11093.25 h60
  text "4.8" at 17260.58,11093.25 h60
  text "5" at 14401.32,10973.25 h60
  text "Signal Layer 4" at 14811.23,10973.25 h60
  text "2.76mil" at 16610.74,10973.25 h60
  text "Dielectric4" at 14811.23,10853.25 h60
  text "FR-4 High Tg" at 15750.97,10853.25 h60
  text "5.00mil" at 16610.74,10853.25 h60
  text "4.8" at 17260.58,10853.25 h60
  text "6" at 14401.32,10733.25 h60
  text "Signal Layer 5" at 14811.23,10733.25 h60
  text "2.76mil" at 16610.74,10733.25 h60
  text "Dielectric6" at 14811.23,10613.25 h60
  text "FR-4 High Tg" at 15750.97,10613.25 h60
  text "5.00mil" at 16610.74,10613.25 h60
  text "4.8" at 17260.58,10613.25 h60
  text "7" at 14401.32,10493.25 h60
  text "Signal Layer 6" at 14811.23,10493.25 h60
  text "2.76mil" at 16610.74,10493.25 h60
  text "Dielectric5" at 14811.23,10373.25 h60
  text "FR-4 High Tg" at 15750.97,10373.25 h60
  text "5.00mil" at 16610.74,10373.25 h60
  text "4.8" at 17260.58,10373.25 h60
  text "8" at 14401.32,10253.25 h60
  text "Bottom Layer" at 14811.23,10253.25 h60
  text "2.76mil" at 16610.74,10253.25 h60
  text "Bottom Solder" at 14811.23,10133.25 h60
  text "Solder Resist" at 15750.97,10133.25 h60
  text "0.40mil" at 16610.74,10133.25 h60
  text "3.5" at 17260.58,10133.25 h60
  text "Bottom Overlay" at 14811.23,10013.25 h60
  text ".Layer_Name" at 373.26,-1656.72 h60
M13 Component Bodies Top:
  text ".Layer_Name" at 373.26,-1656.72 h60
M14 Component Bodies Bottom:
  text ".Layer_Name" at 373.26,-1656.72 h60
M15 Courtyards Top:
  text ".Layer_Name" at 373.26,-1656.72 h60
M16 Courtyards Bottom:
  text ".Layer_Name" at 373.26,-1656.72 h60
Drill Drawing:
  circle w10: c6064.03,5292.61 r16.58
  circle w10: c6064.03,5292.61 r27.63
  circle w10: c6064.03,4919.65 r27.63
  lines w10: 6036.41,5016.35 6091.66,5016.35 6091.66,5071.6 6036.41,5071.6 6036.41,5016.35 ; 6036.41,5140.67 6091.66,5140.67 6091.66,5195.92 6036.41,5195.92 6036.41,5140.67 ; 6036.41,5403.12 6050.22,5403.12 6064.03,5389.31 6077.85,5403.12 6091.66,5403.12 6077.85,5416.93 6091.66,5430.75 6077.85,5430.75 6064.03,5444.56 6050.22,5430.75 6036.41,5430.75 6050.22,5416.93 6036.41,5403.12 ; 6036.41,5527.44 6050.22,5527.44 6050.22,5513.63 6077.85,5513.63 6077.85,5527.44 6091.66,5527.44 6091.66,5555.07 6077.85,5555.07 6077.85,5568.88 6050.22,5568.88 6050.22,5555.07 6036.41,5555.07 6036.41,5527.44 ; 6036.41,5637.95 6036.41,5651.76 6050.22,5665.57 6036.41,5679.39 6036.41,5693.2 6050.22,5693.2 6064.03,5679.39 6077.85,5693.2 6091.66,5693.2 6091.66,5679.39 6077.85,5665.57 6091.66,5651.76 6091.66,5637.95 6077.85,5637.95 6064.03,5651.76 6050.22,5637.95 6036.41,5637.95 ; 6036.41,5789.89 6064.03,5762.27 6091.66,5789.89 6064.03,5817.52 6036.41,5789.89 ; 6036.41,5886.59 6064.03,5900.4 6091.66,5886.59 6077.85,5914.21 6091.66,5941.84 6064.03,5928.03 6036.41,5941.84 6050.22,5914.21 6036.41,5886.59 ; 6047.46,5027.4 6080.61,5027.4 6080.61,5060.55 6047.46,5060.55 6047.46,5027.4
  lines w12: 5986.31,4854.73 9171.32,4854.73 ; 5986.31,5973.61 9171.32,5973.61 ; 6324.18,4730.41 6324.18,6097.93 ; 6653.46,4730.41 6653.46,6097.93 ; 7246.25,4730.41 7246.25,6097.93 ; 7505.39,4730.41 7505.39,6097.93 ; 7880.55,4730.41 7880.55,6097.93 ; 8604.88,4730.41 8604.88,6097.93 ; 5986.31,4730.41 9171.32,4730.41 9171.32,6097.93 5986.31,6097.93 5986.31,4730.41
  text "Symbol" at 6060.91,6010.91 h72
  text "Count" at 6361.47,6010.91 h72
  text "Hole Size" at 6690.75,6010.91 h72
  text "Plated" at 7283.55,6010.91 h72
  text "Hole Type" at 7542.69,6010.91 h72
  text "Drill Layer Pair" at 7917.85,6010.91 h72
  text "Hole Tolerance" at 8642.18,6010.91 h72
  text "39" at 6361.47,5886.59 h60
  text "7.87mil (0.200mm)" at 6690.75,5886.59 h60
  text "PTH" at 7283.55,5886.59 h60
  text "Round" at 7542.69,5886.59 h60
  text "Top Layer - Bottom Layer" at 7917.85,5886.59 h60
  text "207" at 6361.47,5762.27 h60
  text "8.00mil (0.203mm)" at 6690.75,5762.27 h60
  text "PTH" at 7283.55,5762.27 h60
  text "Round" at 7542.69,5762.27 h60
  text "Top Layer - Bottom Layer" at 7917.85,5762.27 h60
  text "229" at 6361.47,5637.95 h60
  text "10.00mil (0.254mm)" at 6690.75,5637.95 h60
  text "PTH" at 7283.55,5637.95 h60
  text "Round" at 7542.69,5637.95 h60
  text "Top Layer - Bottom Layer" at 7917.85,5637.95 h60
  text "570" at 6361.47,5513.63 h60
  text "16.00mil (0.406mm)" at 6690.75,5513.63 h60
  text "PTH" at 7283.55,5513.63 h60
  text "Round" at 7542.69,5513.63 h60
  text "Top Layer - Bottom Layer" at 7917.85,5513.63 h60
  text "2" at 6361.47,5389.31 h60
  text "37.99mil (0.965mm)" at 6690.75,5389.31 h60
  text "PTH" at 7283.55,5389.31 h60
  text "Round" at 7542.69,5389.31 h60
  text "Top Layer - Bottom Layer" at 7917.85,5389.31 h60
  text "10" at 6361.47,5264.99 h60
  text "40.00mil (1.016mm)" at 6690.75,5264.99 h60
  text "PTH" at 7283.55,5264.99 h60
  text "Round" at 7542.69,5264.99 h60
  text "Top Layer - Bottom Layer" at 7917.85,5264.99 h60
  text "204" at 6361.47,5140.67 h60
  text "45.28mil (1.150mm)" at 6690.75,5140.67 h60
  text "PTH" at 7283.55,5140.67 h60
  text "Round" at 7542.69,5140.67 h60
  text "Top Layer - Bottom Layer" at 7917.85,5140.67 h60
  text "4" at 6361.47,5016.35 h60
  text "125.98mil (3.200mm)" at 6690.75,5016.35 h60
  text "PTH" at 7283.55,5016.35 h60
  text "Round" at 7542.69,5016.35 h60
  text "Top Layer - Bottom Layer" at 7917.85,5016.35 h60
  text "4" at 6361.47,4892.03 h60
  text "270.00mil (6.858mm)" at 6690.75,4892.03 h60
  text "PTH" at 7283.55,4892.03 h60
  text "Round" at 7542.69,4892.03 h60
  text "Top Layer - Bottom Layer" at 7917.85,4892.03 h60
  text "1269 Total" at 6361.47,4767.71 h60
  text ".Layer_Name" at 373.26,-1656.72 h60
M17 Embedded Cavity:
  text ".Layer_Name" at 373.26,-1656.72 h60
M18 Embedded Assembly:
  text ".Layer_Name" at 373.26,-1656.72 h60
M19 Embedded Keepout:
  text ".Layer_Name" at 363.26,-1656.72 h60

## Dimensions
0,0 to 20.67,6100.39 on M2 Board Dimensions
0,0 to 5600,0 on M2 Board Dimensions
-203.74,-1198.23 to 796.26,-1198.23 on M2 Board Dimensions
